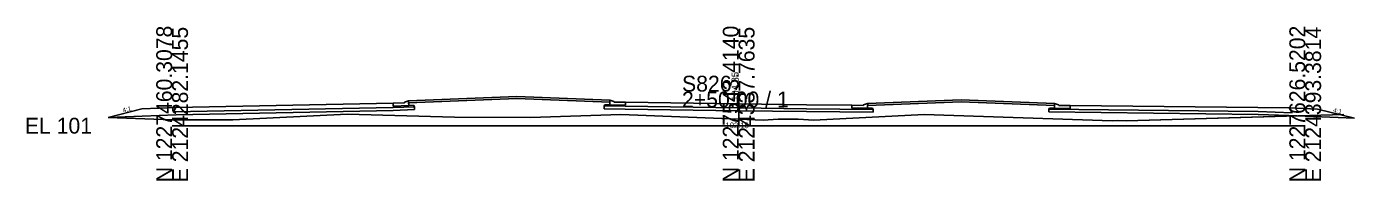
# Model space of a CAD drawing. Extents: x 2118382 to 2118616, y 1213030 to 1222057.
# Drawn here: x 2118381.9 to 2118616.3, y 1213030.1 to 1213057.3 of the extents above; entities that cross this region are included whole.
import ezdxf

# ---------------------------------------------------------------- set-up
doc = ezdxf.new("R2010")
doc.units = 0
for name, color, linetype in [('TS_CURB_GUTTER', 7, 'Continuous'), ('XS_CELL', 7, 'Continuous'), ('XS_M_SHAPES_EARTHWORK', 7, 'Continuous'), ('XS_P_CONCRETE', 7, 'Continuous'), ('XS_P_FINISHED_GRADE', 7, 'Continuous'), ('XS_P_FINISHED_GRADE_ELEV_TX', 7, 'Continuous'), ('XS_P_SUBGRADE_GRANULAR', 7, 'Continuous'), ('XS_P_SUBGRADE_GRANULAR_B', 7, 'Continuous'), ('XS_P_SUBGRADE_PAVEMENT', 7, 'Continuous'), ('XS_P_TX_FS_BS', 7, 'Continuous'), ('XS_X_GROUND', 7, 'Continuous'), ('XS_X_GROUND_TX', 7, 'Continuous')]:
    doc.layers.add(name, color=color, linetype=linetype)

msp = doc.modelspace()

# ---------------------------------------------------------------- linework, layer by layer
at = {"layer": 'TS_CURB_GUTTER'}
for points in [[(2118449.34, 1213044.19), (2118449.36, 1213043.37), (2118446.61, 1213043.26), (2118446.59, 1213043.76), (2118448.59, 1213043.84), (2118448.59, 1213043.86), (2118448.59, 1213043.89), (2118448.6, 1213043.91), (2118448.61, 1213043.93), (2118448.64, 1213043.95), (2118449.32, 1213044.2), (2118449.33, 1213044.2), (2118449.33, 1213044.2), (2118449.33, 1213044.2), (2118449.34, 1213044.19), (2118449.34, 1213044.19)], [(2118484.85, 1213044.3), (2118484.85, 1213043.48), (2118487.6, 1213043.44), (2118487.6, 1213043.94), (2118485.6, 1213043.97), (2118485.6, 1213043.99), (2118485.6, 1213044.02), (2118485.59, 1213044.04), (2118485.57, 1213044.06), (2118485.54, 1213044.07), (2118484.86, 1213044.31), (2118484.86, 1213044.31), (2118484.85, 1213044.31), (2118484.85, 1213044.31), (2118484.85, 1213044.3), (2118484.85, 1213044.3)], [(2118530.37, 1213043.7), (2118530.35, 1213042.89), (2118527.6, 1213042.92), (2118527.6, 1213043.42), (2118529.6, 1213043.4), (2118529.6, 1213043.42), (2118529.61, 1213043.44), (2118529.62, 1213043.46), (2118529.63, 1213043.48), (2118529.66, 1213043.5), (2118530.35, 1213043.71), (2118530.36, 1213043.72), (2118530.36, 1213043.71), (2118530.37, 1213043.71), (2118530.37, 1213043.71), (2118530.37, 1213043.7)], [(2118566.12, 1213043.35), (2118566.11, 1213042.85), (2118563.36, 1213042.89), (2118563.36, 1213043.7), (2118563.36, 1213043.71), (2118563.36, 1213043.71), (2118563.37, 1213043.72), (2118563.37, 1213043.71), (2118564.06, 1213043.48), (2118564.09, 1213043.46), (2118564.11, 1213043.43), (2118564.12, 1213043.4), (2118564.12, 1213043.38), (2118566.12, 1213043.35)]]:
    msp.add_lwpolyline(points, dxfattribs=at)
at = {"layer": 'XS_CELL'}
for p, q in [((2118507.6, 1213039.8), (2118507.6, 1213045.84)), ((2118407.6, 1213039.8), (2118507.6, 1213039.8)), ((2118507.6, 1213039.8), (2118607.6, 1213039.8))]:
    msp.add_line(p, q, dxfattribs=at)
at = {"layer": 'XS_M_SHAPES_EARTHWORK'}
for p, q in [((2118446.61, 1213042.51), (2118408.3, 1213041.75)), ((2118450.36, 1213042.66), (2118446.61, 1213042.51)), ((2118468.47, 1213044.63), (2118449.34, 1213043.87)), ((2118449.34, 1213043.87), (2118449.36, 1213043.37)), ((2118449.36, 1213043.37), (2118450.22, 1213043.41)), ((2118450.22, 1213043.41), (2118450.36, 1213043.16)), ((2118450.36, 1213043.16), (2118450.36, 1213042.66)), ((2118484.85, 1213043.98), (2118468.47, 1213044.63)), ((2118483.85, 1213043.29), (2118483.97, 1213043.49)), ((2118483.85, 1213042.79), (2118483.85, 1213043.29)), ((2118487.59, 1213042.73), (2118483.85, 1213042.79)), ((2118483.97, 1213043.49), (2118484.85, 1213043.48)), ((2118484.85, 1213043.48), (2118484.85, 1213043.98)), ((2118507.59, 1213042.44), (2118487.59, 1213042.73)), ((2118530.36, 1213043.38), (2118530.35, 1213042.89)), ((2118530.35, 1213042.89), (2118531.22, 1213042.88)), ((2118546.86, 1213044.04), (2118530.36, 1213043.38)), ((2118531.22, 1213042.88), (2118531.34, 1213042.67)), ((2118531.34, 1213042.67), (2118531.34, 1213042.17)), ((2118563.36, 1213043.38), (2118546.86, 1213044.04)), ((2118562.36, 1213042.73), (2118562.45, 1213042.89)), ((2118562.36, 1213042.23), (2118562.36, 1213042.73)), ((2118562.45, 1213042.89), (2118563.36, 1213042.89)), ((2118563.36, 1213042.89), (2118563.36, 1213043.38)), ((2118408.3, 1213041.75), (2118396.32, 1213041.27)), ((2118396.32, 1213041.27), (2118407.6, 1213040.83)), ((2118407.6, 1213040.83), (2118416.46, 1213040.86)), ((2118416.46, 1213040.86), (2118418.34, 1213040.86)), ((2118418.34, 1213040.86), (2118438.51, 1213041.82)), ((2118438.51, 1213041.82), (2118457.47, 1213041.29)), ((2118457.47, 1213041.29), (2118470.86, 1213041.26)), ((2118470.86, 1213041.26), (2118486.81, 1213041.79)), ((2118486.81, 1213041.79), (2118507.6, 1213040.96)), ((2118519.59, 1213042.3), (2118507.59, 1213042.44)), ((2118507.6, 1213040.96), (2118511.91, 1213040.79)), ((2118511.91, 1213040.79), (2118514.56, 1213040.94)), ((2118514.56, 1213040.94), (2118516.39, 1213040.98)), ((2118516.39, 1213040.98), (2118518.12, 1213040.95)), ((2118518.12, 1213040.95), (2118520.86, 1213040.78)), ((2118531.34, 1213042.17), (2118519.59, 1213042.3)), ((2118520.86, 1213040.78), (2118540.32, 1213041.77)), ((2118540.32, 1213041.77), (2118573.53, 1213040.67)), ((2118599.31, 1213041.8), (2118562.36, 1213042.23)), ((2118573.53, 1213040.67), (2118574.38, 1213040.74)), ((2118574.38, 1213040.74), (2118576.07, 1213040.66)), ((2118576.07, 1213040.66), (2118606.18, 1213041.52)), ((2118604.71, 1213041.58), (2118599.31, 1213041.8)), ((2118606.18, 1213041.52), (2118604.71, 1213041.58))]:
    msp.add_line(p, q, dxfattribs=at)
msp.add_lwpolyline([(2118449.34, 1213043.87), (2118449.34, 1213043.87)], dxfattribs=at)
at = {"layer": 'XS_P_CONCRETE'}
for p, q in [((2118468.47, 1213044.63), (2118449.34, 1213043.87)), ((2118484.85, 1213043.98), (2118468.47, 1213044.63)), ((2118530.36, 1213043.38), (2118546.86, 1213044.04)), ((2118563.36, 1213043.38), (2118546.86, 1213044.04))]:
    msp.add_line(p, q, dxfattribs=at)
at = {"layer": 'XS_P_FINISHED_GRADE'}
for p, q in [((2118468.47, 1213044.96), (2118449.33, 1213044.2)), ((2118484.85, 1213044.31), (2118468.47, 1213044.96)), ((2118402.28, 1213042.76), (2118396.32, 1213041.27)), ((2118408.28, 1213043), (2118402.28, 1213042.76)), ((2118446.59, 1213043.76), (2118408.28, 1213043)), ((2118507.6, 1213043.65), (2118487.6, 1213043.94)), ((2118507.6, 1213043.65), (2118519.6, 1213043.51)), ((2118519.6, 1213043.51), (2118527.6, 1213043.42)), ((2118530.36, 1213043.72), (2118546.86, 1213044.38)), ((2118563.37, 1213043.71), (2118546.86, 1213044.38)), ((2118566.12, 1213043.35), (2118604.76, 1213042.95)), ((2118604.76, 1213042.95), (2118609.76, 1213042.75)), ((2118609.76, 1213042.75), (2118616.29, 1213041.12))]:
    msp.add_line(p, q, dxfattribs=at)
at = {"layer": 'XS_P_SUBGRADE_GRANULAR'}
for p, q in [((2118446.61, 1213042.51), (2118408.3, 1213041.75)), ((2118446.61, 1213042.51), (2118450.36, 1213042.66)), ((2118450.36, 1213042.66), (2118450.36, 1213043.16)), ((2118483.85, 1213042.79), (2118483.85, 1213043.29)), ((2118487.59, 1213043.23), (2118483.85, 1213043.29)), ((2118487.59, 1213042.73), (2118483.85, 1213042.79)), ((2118507.59, 1213042.44), (2118487.59, 1213042.73)), ((2118531.34, 1213042.17), (2118531.34, 1213042.67)), ((2118562.36, 1213042.23), (2118562.36, 1213042.73)), ((2118408.3, 1213041.75), (2118396.32, 1213041.27)), ((2118507.59, 1213042.44), (2118519.59, 1213042.3)), ((2118519.59, 1213042.3), (2118531.34, 1213042.17)), ((2118562.36, 1213042.23), (2118599.31, 1213041.8)), ((2118599.31, 1213041.8), (2118604.71, 1213041.58)), ((2118604.71, 1213041.58), (2118616.29, 1213041.12))]:
    msp.add_line(p, q, dxfattribs=at)
at = {"layer": 'XS_P_SUBGRADE_GRANULAR_B'}
for p, q in [((2118449.36, 1213043.37), (2118450.22, 1213043.41)), ((2118450.36, 1213043.16), (2118450.22, 1213043.41)), ((2118483.85, 1213043.29), (2118483.97, 1213043.49)), ((2118484.85, 1213043.48), (2118483.97, 1213043.49)), ((2118530.35, 1213042.89), (2118531.22, 1213042.88)), ((2118531.34, 1213042.67), (2118531.22, 1213042.88)), ((2118562.36, 1213042.73), (2118562.45, 1213042.89)), ((2118563.36, 1213042.89), (2118562.45, 1213042.89))]:
    msp.add_line(p, q, dxfattribs=at)
at = {"layer": 'XS_P_SUBGRADE_PAVEMENT'}
for p, q in [((2118446.6, 1213043.01), (2118407.84, 1213042.24)), ((2118408.28, 1213043), (2118407.84, 1213042.24)), ((2118446.6, 1213043.01), (2118450.36, 1213043.16)), ((2118507.59, 1213042.94), (2118487.59, 1213043.23)), ((2118507.59, 1213042.94), (2118519.59, 1213042.8)), ((2118519.59, 1213042.8), (2118531.34, 1213042.67)), ((2118562.36, 1213042.73), (2118599.31, 1213042.3)), ((2118604.76, 1213042.95), (2118605.28, 1213042.06)), ((2118599.31, 1213042.3), (2118605.28, 1213042.06))]:
    msp.add_line(p, q, dxfattribs=at)
at = {"layer": 'XS_X_GROUND'}
for p, q in [((2118407.6, 1213040.83), (2118396.32, 1213041.27)), ((2118407.6, 1213040.83), (2118416.46, 1213040.86)), ((2118416.46, 1213040.86), (2118418.34, 1213040.86)), ((2118418.34, 1213040.86), (2118438.51, 1213041.82)), ((2118438.51, 1213041.82), (2118457.47, 1213041.29)), ((2118457.47, 1213041.29), (2118470.86, 1213041.26)), ((2118470.86, 1213041.26), (2118486.81, 1213041.79)), ((2118486.81, 1213041.79), (2118507.6, 1213040.96)), ((2118507.6, 1213040.96), (2118511.91, 1213040.79)), ((2118511.91, 1213040.79), (2118514.56, 1213040.94)), ((2118514.56, 1213040.94), (2118516.39, 1213040.98)), ((2118516.39, 1213040.98), (2118518.12, 1213040.95)), ((2118518.12, 1213040.95), (2118520.86, 1213040.78)), ((2118520.86, 1213040.78), (2118540.32, 1213041.77)), ((2118540.32, 1213041.77), (2118573.53, 1213040.67)), ((2118573.53, 1213040.67), (2118574.38, 1213040.74)), ((2118574.38, 1213040.74), (2118576.07, 1213040.66)), ((2118576.07, 1213040.66), (2118614.4, 1213041.76))]:
    msp.add_line(p, q, dxfattribs=at)

# ---------------------------------------------------------------- texts
at = {"layer": 'XS_CELL'}
for s, p in [('N 1227460.3078', (2118407.6, 1213029.8)), ('E 2124282.1455', (2118410.4, 1213029.8)), ('N 1227543.4140', (2118507.6, 1213029.8)), ('E 2124337.7635', (2118510.4, 1213029.8)), ('N 1227626.5202', (2118607.6, 1213029.8)), ('E 2124393.3814', (2118610.4, 1213029.8))]:
    msp.add_text(s, height=2.8, rotation=90, dxfattribs=at).set_placement(p)
for s, p in [('S826', (2118497.6, 1213045.84)), ('2+50.00 / 1', (2118497.6, 1213043.04)), ('EL 101', (2118381.6, 1213038.4))]:
    msp.add_text(s, height=2.8, dxfattribs=at).set_placement(p)
at = {"layer": 'XS_P_FINISHED_GRADE_ELEV_TX'}
msp.add_text(' 104.85', height=1.25, rotation=90, dxfattribs=at).set_placement((2118507.6, 1213043.73))
at = {"layer": 'XS_P_TX_FS_BS'}
for rotation, p in [(14.0362, (2118398.96, 1213042.12)), (345.9638, (2118612.47, 1213042.22))]:
    msp.add_text('4:1', height=0.8, rotation=rotation, dxfattribs=at).set_placement(p)
at = {"layer": 'XS_X_GROUND_TX'}
msp.add_text('102.16', height=1, dxfattribs=at).set_placement((2118505.29, 1213039.37))

doc.saveas('drawing.dxf')
